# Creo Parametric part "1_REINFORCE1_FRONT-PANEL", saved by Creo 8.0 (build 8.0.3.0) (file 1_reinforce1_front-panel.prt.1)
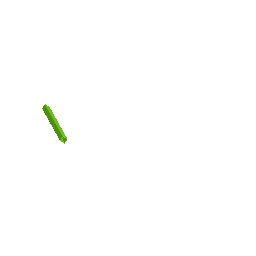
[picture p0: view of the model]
Units: millimeter Newton Second (mmNs); MM, TONNE, SECS

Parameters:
  SMT_DFLT_BEND_REL_LENGTH_TYPE = "Through All"

Other parameters: SMT_THICKNESS, SMT_PART_BEND_ALLOWANCE_FACTOR, SMT_DFLT_BEND_RADIUS, SMT_DFLT_BEND_ANGLE, SMT_DFLT_CRNR_REL_WIDTH, SMT_DFLT_CRNR_REL_DEPTH, SMT_DFLT_BEND_REL_WIDTH, SMT_DFLT_BEND_REL_DEPTH, SMT_DFLT_BEND_REL_LENGTH, SMT_DFLT_BEND_REL_ANGLE, SMT_GAP, SMT_DFLT_EDGE_TREA_WIDTH, SMT_DFLT_MITER_CUT_WIDTH, SMT_DFLT_MITER_CUT_OFFSET

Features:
  1. datum plane "DTM1"
  2. datum plane "DTM2"
  3. datum plane "DTM3"
  4. coordinate system
  5. datum plane "DTM4"
  6. protrusion
  7. round
  8. cut

Other named items: CS0

Layers: 0_ALL_AXIS, 0_ALL_CSYS, 0_ALL_CURVES, 0_ALL_PLANES, 0_ALL_POINTS, 0_ALL_SURFS, REINFORCE1_FRONT-PANEL

Surfaces: 24 plane, 12 cylinder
